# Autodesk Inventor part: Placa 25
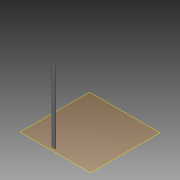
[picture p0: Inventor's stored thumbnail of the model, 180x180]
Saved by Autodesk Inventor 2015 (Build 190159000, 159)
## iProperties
Created: 2015-04
Part Number: Placa 25
Material: Generic
Document SubType Name: Modeling
Designer: suporte
Density: 1 g/cm^3
Appearance: Default
Author: suporte
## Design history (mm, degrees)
workplane "Work Plane1"
sketch "Sketch1"
  geometry: L1 (-187.5, -887.5)-(-175, -887.5) reference; L2 (-187.5, -887.5)-(-87.5, -887.5); L3 (-87.5, -887.5)-(-87.5, -900); L4 (-87.5, -900)-(-187.5, -900); L5 (-187.5, -900)-(-187.5, -887.5); 1 further point
  constraints: 8 end point, 2 parallel, 1 horizontal, 1 perpendicular
extrude "Extrusion1" new body sketch "Sketch1" distance "d0" = 2100; taper "d1" = 0 deg
body "Solid1"
node "Reference1"
node "Reference2"
